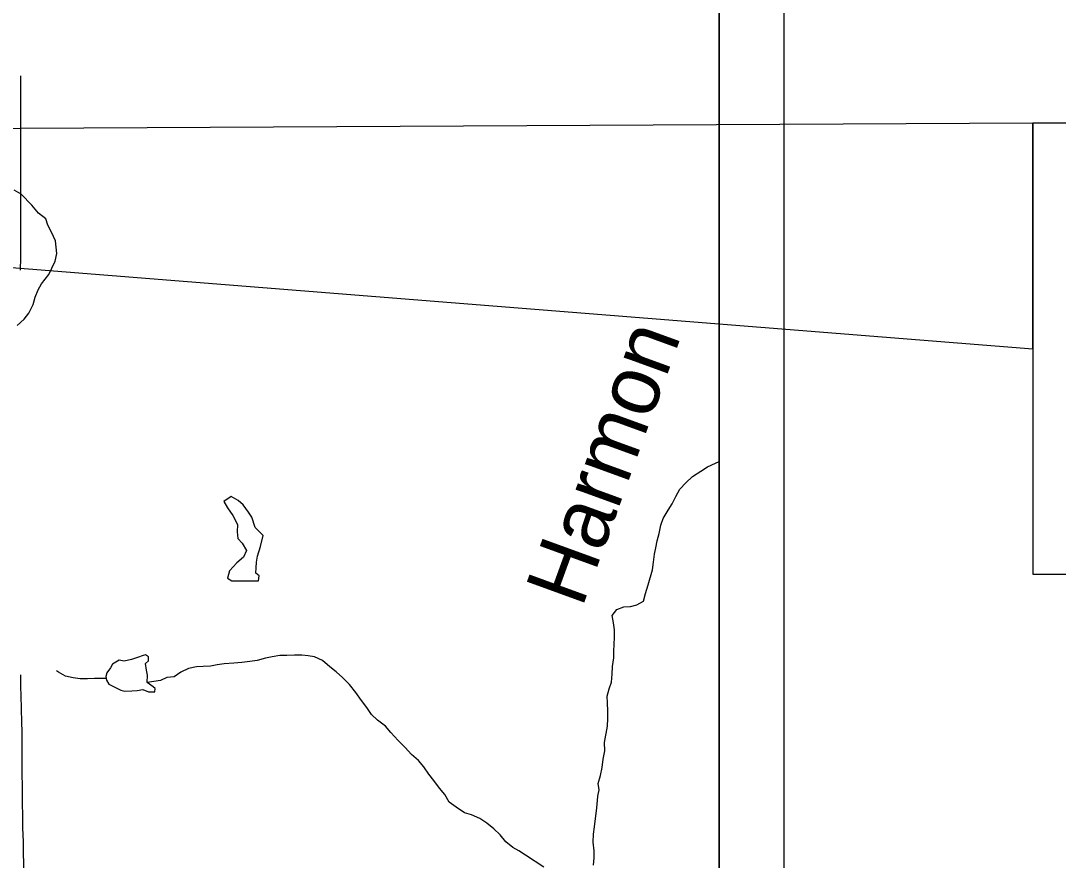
# Model space of a CAD drawing. Extents: x 0 to 34, y 0 to 22.
# Drawn here: x 7.83 to 9.44, y 15.787 to 17.09 of the extents above; entities that cross this region are included whole.
import ezdxf

# ---------------------------------------------------------------- set-up
doc = ezdxf.new("R2010")
doc.units = 0
for name, color, linetype in [('GM_X_Corporation', 7, 'Continuous'), ('GM_X_Minor_Lake', 7, 'Continuous'), ('GM_X_Minor_River', 7, 'Continuous'), ('GM_X_Minor_River_Text', 7, 'Continuous'), ('GM_X_State_Route', 7, 'Continuous'), ('SH_Data', 7, 'Continuous'), ('SH_Text', 7, 'Continuous')]:
    doc.layers.add(name, color=color, linetype=linetype)

msp = doc.modelspace()

# ---------------------------------------------------------------- linework, layer by layer
at = {"layer": 'GM_X_Corporation'}
msp.add_lwpolyline([(5.0539, 13.8173), (8.914, 13.8173), (8.914, 17.2449), (8.8621, 17.2445), (8.8285, 17.2444), (8.762, 17.244), (8.6974, 17.2434), (8.6851, 17.2432), (8.6445, 17.2426), (8.5818, 17.2419), (8.5289, 17.2412), (8.4823, 17.2409), (8.4071, 17.2399), (8.3164, 17.2393), (8.2474, 17.2382), (8.2138, 17.2377), (8.1597, 17.237), (8.1363, 17.2369), (8.0417, 17.237), (8.015, 17.2365), (7.9908, 17.2361), (7.8566, 17.2348), (7.8362, 17.2347), (7.6782, 17.2342)], dxfattribs=at)
at = {"layer": 'GM_X_Minor_Lake'}
for p, q in [((8.1576, 16.2208), (8.1992, 16.2209)), ((7.967, 16.0606), (7.9853, 16.051))]:
    msp.add_line(p, q, dxfattribs=at)
for points in [[(8.1992, 16.2209), (8.2003, 16.2288), (8.1949, 16.233), (8.1956, 16.2413), (8.1962, 16.2497), (8.1977, 16.2592), (8.2024, 16.274), (8.2064, 16.2912), (8.1941, 16.3039), (8.1886, 16.3198), (8.1836, 16.3277), (8.1755, 16.3386), (8.1675, 16.3458), (8.1565, 16.3517), (8.1452, 16.344), (8.151, 16.3342), (8.1594, 16.3221), (8.1664, 16.3085), (8.1662, 16.2968), (8.167, 16.2865), (8.1736, 16.2794), (8.1805, 16.2681), (8.1757, 16.2578), (8.1652, 16.2486), (8.154, 16.2363), (8.1511, 16.2252), (8.1576, 16.2208)], [(7.9853, 16.051), (7.9917, 16.0499), (8.0023, 16.05), (8.011, 16.0505), (8.0194, 16.0521), (8.0285, 16.0484), (8.0383, 16.0485), (8.039, 16.0539), (8.0356, 16.0565), (8.0264, 16.0632), (8.0271, 16.0746), (8.0255, 16.0822), (8.0238, 16.0924), (8.0283, 16.0966), (8.0286, 16.1031), (8.0237, 16.1061), (8.0199, 16.1049), (8.0116, 16.1018), (8.0022, 16.0986), (7.9905, 16.0962), (7.9829, 16.0976), (7.9723, 16.0914), (7.9694, 16.0857), (7.9638, 16.078), (7.9623, 16.0723), (7.9631, 16.0667), (7.967, 16.0606)]]:
    msp.add_lwpolyline(points, dxfattribs=at)
at = {"layer": 'GM_X_Minor_River'}
for points in [[(7.8247, 16.6173), (7.8356, 16.627), (7.8426, 16.6365), (7.8493, 16.6499), (7.8526, 16.6609), (7.8574, 16.6724), (7.8622, 16.6819), (7.8738, 16.6961), (7.8782, 16.706), (7.8834, 16.7171), (7.8863, 16.7289), (7.885, 16.7388), (7.8842, 16.7486), (7.878, 16.7622), (7.8721, 16.7728), (7.869, 16.7826), (7.8575, 16.7912), (7.8472, 16.804), (7.8307, 16.8209), (7.82, 16.8272)], [(8.719, 15.7794), (8.7196, 15.7908), (8.7198, 15.8018), (8.7185, 15.8151), (8.7188, 15.828), (8.7202, 15.839), (8.7219, 15.8519), (8.7233, 15.8637), (8.7243, 15.8736), (8.7257, 15.8865), (8.7275, 15.8964), (8.7262, 15.9066), (8.7295, 15.9188), (8.732, 15.9314), (8.7337, 15.9439), (8.7362, 15.9572), (8.7361, 15.9701), (8.7404, 15.9956), (8.741, 16.007), (8.7412, 16.0184), (8.7403, 16.0317), (8.7402, 16.0419), (8.7431, 16.0534), (8.7468, 16.0636), (8.7478, 16.0762), (8.7484, 16.088), (8.7501, 16.1013), (8.7504, 16.1123), (8.7507, 16.1218), (8.7513, 16.1339), (8.7515, 16.1446), (8.7499, 16.1559), (8.7475, 16.1669), (8.755, 16.1765), (8.7659, 16.1804), (8.7761, 16.1813), (8.7859, 16.1837), (8.7965, 16.1891), (8.7997, 16.2013), (8.8038, 16.2146), (8.8103, 16.2382), (8.8121, 16.25), (8.8134, 16.2622), (8.8156, 16.2721), (8.8174, 16.2831), (8.8207, 16.2942), (8.8235, 16.3075), (8.8268, 16.3174), (8.8346, 16.3308), (8.8406, 16.3403), (8.8465, 16.3518), (8.8528, 16.3633), (8.8622, 16.3729), (8.8723, 16.3828), (8.8851, 16.391), (8.8956, 16.3979), (8.908, 16.4034), (8.914, 16.4061)], [(8.2551, 16.1057), (8.243, 16.1048), (8.232, 16.1051), (8.2203, 16.1027), (8.2101, 16.1007), (8.1972, 16.0975), (8.1855, 16.0958), (8.173, 16.0942), (8.1609, 16.0929), (8.1458, 16.0923), (8.1348, 16.0903), (8.1246, 16.0883), (8.1133, 16.0878), (8.1027, 16.0873), (8.0906, 16.0848), (8.0785, 16.0794), (8.068, 16.072), (8.057, 16.0708), (8.0468, 16.0661), (8.0264, 16.0632)], [(8.6417, 15.7766), (8.6131, 15.7952), (8.6032, 15.8019), (8.5937, 15.8071), (8.583, 15.8158), (8.5741, 15.8267), (8.5642, 15.836), (8.5535, 15.8446), (8.5424, 15.8521), (8.5295, 15.8576), (8.5188, 15.8606), (8.5058, 15.8699), (8.4951, 15.8774), (8.4882, 15.8894), (8.4797, 15.8992), (8.4709, 15.9109), (8.4632, 15.9206), (8.4555, 15.9323), (8.4471, 15.9421), (8.4364, 15.9515), (8.4264, 15.9624), (8.416, 15.9729), (8.4045, 15.9856), (8.3961, 15.9954), (8.3839, 16.0044), (8.3743, 16.0134), (8.367, 16.0243), (8.3589, 16.0352), (8.35, 16.0476), (8.3401, 16.06), (8.3293, 16.0709), (8.3198, 16.0795), (8.3098, 16.0874), (8.2983, 16.0975), (8.2862, 16.1031), (8.2759, 16.1045), (8.2661, 16.1055), (8.2551, 16.1057)], [(7.9628, 16.0691), (7.9446, 16.0695), (7.9336, 16.0686), (7.9222, 16.0688), (7.9116, 16.0702), (7.8998, 16.0731), (7.8888, 16.0791), (7.8857, 16.0813)]]:
    msp.add_lwpolyline(points, dxfattribs=at)
at = {"layer": 'GM_X_State_Route'}
for points in [[(7.83, 16.703), (7.8302, 16.7225), (7.8303, 16.7325), (7.8305, 16.7976), (7.8303, 16.8628), (7.8303, 16.942), (7.8303, 16.9638), (7.8303, 16.9728), (7.8302, 16.9796), (7.8301, 17.0048)], [(7.8345, 15.8006), (7.8344, 15.8056), (7.8343, 15.8156), (7.8337, 15.8378), (7.8334, 15.8509), (7.8332, 15.8608), (7.8331, 15.8714), (7.833, 15.8994), (7.8326, 15.9232), (7.8326, 15.9389), (7.8325, 15.9438), (7.8323, 15.9494), (7.8324, 15.9575), (7.8325, 15.9736), (7.8324, 15.9867), (7.8321, 16.0015), (7.8307, 16.0429), (7.8304, 16.0565), (7.8302, 16.0751)], [(7.8349, 15.7733), (7.8349, 15.7796), (7.8345, 15.8006)]]:
    msp.add_lwpolyline(points, dxfattribs=at)
at = {"layer": 'SH_Data'}
for p, q in [((9.014, 20.7173), (9.014, 13.7173)), ((8.914, 20.6173), (8.914, 13.8173))]:
    msp.add_line(p, q, dxfattribs=at)
at = {"layer": 'SH_Text'}
for points in [[(9.4006, 16.931), (5.2772, 16.9092), (9.4006, 16.581)], [(9.4006, 16.231), (11.1382, 16.231), (11.1382, 16.931), (9.4006, 16.931)]]:
    msp.add_lwpolyline(points, close=True, dxfattribs=at)

# ---------------------------------------------------------------- texts
at = {"layer": 'GM_X_Minor_River_Text'}
msp.add_text('Harmon', height=0.09471, rotation=69.9863, dxfattribs=at).set_placement((8.7009, 16.1774))

doc.saveas('drawing.dxf')
